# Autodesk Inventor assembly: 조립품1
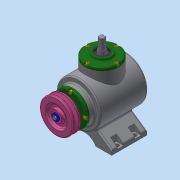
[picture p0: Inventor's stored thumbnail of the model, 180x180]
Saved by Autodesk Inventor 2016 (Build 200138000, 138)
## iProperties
Created: 2021-04
Part Number: 조립품1
Document SubType Name: Assembly
Designer: User
Author: User
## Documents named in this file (17)
- C:\Users\User\Desktop\710407V1008 (1)\조립품1.iam
- C:\Users\User\Desktop\710407V1008 (1)\본체.ipt
- C:\Users\User\Desktop\710407V1008 (1)\서브 축.ipt
- 서브 축.ipt
- C:\Users\User\Desktop\710407V1008 (1)\베어링 6203.ipt
- C:\Users\User\Desktop\710407V1008 (1)\메인 축.ipt
- 메인 축.ipt
- C:\Users\User\Desktop\710407V1008 (1)\커버.ipt
- C:\Users\User\Desktop\710407V1008 (1)\키 4 x 4 x 14.ipt
- C:\Users\User\Desktop\710407V1008 (1)\키 5 x 5 x 14.ipt
- C:\Users\User\Desktop\710407V1008 (1)\서브 베벨기어.ipt
- C:\Users\User\Desktop\710407V1008 (1)\메인 베벨기어.ipt
- C:\Users\User\Desktop\710407V1008 (1)\V-벨트풀리.ipt
- C:\Users\User\Desktop\710407V1008 (1)\와셔 4 x 16.ipt
- C:\Users\User\Desktop\710407V1008 (1)\육각볼트 M4 x 8.ipt
- C:\Users\User\Desktop\710407V1008 (1)\오일실 17 x 32 x 8.ipt
- C:\Users\User\Desktop\710407V1008 (1)\볼트 M4 x 10.ipt
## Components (1 placed, 1 different names)
1. V-벨트풀리:1 — 각도:5
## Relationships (1: Angle 1)
- 각도:5 [Angle]: V-벨트풀리:1
